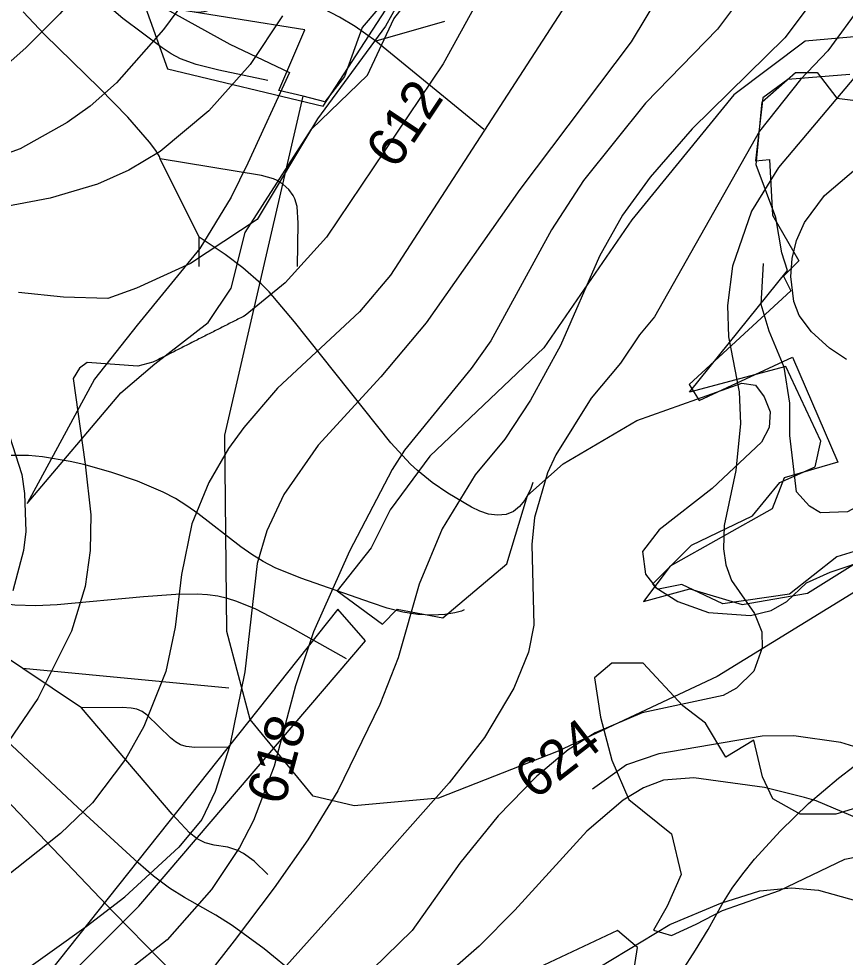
# Model space of a CAD drawing. Extents: x -709584 to -702006, y -1161789 to -1157496.
# Drawn here: x -706673 to -706462.3, y -1159575.6 to -1159336.3 of the extents above; entities that cross this region are included whole.
import ezdxf

# ---------------------------------------------------------------- set-up
doc = ezdxf.new("R2010")
doc.units = 0
for name, color, linetype in [('102_obvod PÚ', 7, 'Continuous'), ('120_vrstevnice hlavní', 7, 'Continuous'), ('121_vrstevnice hlavní_popis', 7, 'Continuous'), ('122_vrstevnice základní', 7, 'Continuous'), ('124_vrstevnice doplňková', 7, 'Continuous'), ('408_BPEJ_linie', 7, 'Continuous'), ('411_akumulovaný odtok', 7, 'Continuous'), ('419_LPIS PB', 7, 'Continuous')]:
    doc.layers.add(name, color=color, linetype=linetype)

msp = doc.modelspace()

# ---------------------------------------------------------------- linework, layer by layer
at = {"layer": '102_obvod PÚ'}
for points in [[(-706646.77, -1159316.53), (-706635.13, -1159349.04), (-706595.43, -1159358.62), (-706572.12, -1159322.59)], [(-706461.16, -1159350.51), (-706476.96, -1159351.76), (-706483.3, -1159356.44), (-706485.18, -1159372.52), (-706481.64, -1159372.18), (-706480.87, -1159386.41), (-706474.14, -1159398.05), (-706478.05, -1159401.96), (-706476.22, -1159405.66), (-706502.09, -1159429.53), (-706499.55, -1159433.61), (-706475.77, -1159422.55), (-706464.19, -1159449.36), (-706477.88, -1159453.35), (-706480.96, -1159461.22), (-706506.97, -1159475.88), (-706513.77, -1159484.9), (-706501.93, -1159481.65), (-706488.59, -1159485.65), (-706471.9, -1159482.71), (-706457.67, -1159473.84)]]:
    msp.add_lwpolyline(points, dxfattribs=at)
at = {"layer": '120_vrstevnice hlavní'}
for points in [[(-706453.14, -1159180.31), (-706463.44, -1159182.02), (-706488.89, -1159188.6), (-706508.34, -1159196.75), (-706527.79, -1159207.05), (-706541.24, -1159216.63), (-706548.67, -1159223.5), (-706554.82, -1159230.94), (-706559.26, -1159240.37), (-706560.97, -1159245.81), (-706562.12, -1159255.53), (-706560.97, -1159270.12), (-706561.12, -1159289.57), (-706563.83, -1159304.16), (-706566.98, -1159313.88), (-706571.41, -1159323.61), (-706579.56, -1159338.2), (-706596.87, -1159361.79), (-706612.27, -1159387.45)], [(-706472.3, -1159333.91), (-706477.74, -1159341.2), (-706501.34, -1159364.37), (-706512.06, -1159376.67), (-706519.07, -1159386.39), (-706524.93, -1159396.83), (-706534.94, -1159419.57), (-706542.52, -1159433.58), (-706549.1, -1159443.45), (-706556.68, -1159452.61), (-706565.12, -1159466.33), (-706570.98, -1159480.49), (-706576.28, -1159499.23), (-706580.99, -1159511.1), (-706591.69, -1159533.16), (-706599.36, -1159545.61), (-706607.91, -1159557.89), (-706618.07, -1159571.37), (-706627.76, -1159583.84)], [(-706612.27, -1159387.46), (-706629.24, -1159398.66), (-706643.01, -1159405.02)], [(-706643.01, -1159405.02), (-706650.29, -1159407.66), (-706661.58, -1159407.24), (-706673.06, -1159406.06)], [(-706675.4, -1159442.75), (-706672.26, -1159452.47), (-706671.55, -1159457.32), (-706671.26, -1159467.04), (-706671.83, -1159471.9), (-706674.55, -1159482.18)]]:
    msp.add_lwpolyline(points, dxfattribs=at)
msp.add_open_spline([(-706612.27, -1159387.45), (-706612.27, -1159387.46)], degree=1, dxfattribs=at)
at = {"layer": '122_vrstevnice základní'}
for points in [[(-706448.85, -1159190.89), (-706463.72, -1159192.18), (-706495.9, -1159204.33), (-706525.65, -1159220.92), (-706535.66, -1159230.36), (-706540.67, -1159237.23), (-706543.67, -1159246.38), (-706544.81, -1159257.82), (-706543.81, -1159287.57), (-706545.24, -1159301.3), (-706549.96, -1159317.32), (-706555.68, -1159331.04), (-706564.83, -1159347.78), (-706594.53, -1159392.02), (-706605.09, -1159403.59), (-706615.32, -1159411.99)], [(-706450, -1159202.05), (-706465.44, -1159204.05), (-706477.02, -1159208.91), (-706485.89, -1159213.92), (-706495.76, -1159218.49), (-706509.77, -1159227.65), (-706514.21, -1159232.08), (-706520.36, -1159241.23), (-706522.36, -1159245.81), (-706524.65, -1159257.25), (-706524.22, -1159266.4), (-706521.21, -1159284.71), (-706520.79, -1159298.44), (-706521.93, -1159306.59), (-706526.51, -1159319.6), (-706532.51, -1159331.04), (-706578.28, -1159401.69), (-706586.14, -1159410.99), (-706607.09, -1159430.51), (-706615.66, -1159440.48), (-706619.55, -1159445.89)], [(-706590.33, -1159211.59), (-706594.67, -1159221.73), (-706609.26, -1159257.6), (-706614.97, -1159269.6), (-706620.54, -1159279.31), (-706635.83, -1159302.6), (-706648.12, -1159318.17), (-706662.55, -1159335.03), (-706671.26, -1159343.75), (-706679.55, -1159351.03), (-706688.69, -1159357.75), (-706694.69, -1159361.32), (-706708.98, -1159367.75), (-706726.12, -1159373.03), (-706741.26, -1159376.46), (-706746.98, -1159378.75), (-706754.27, -1159383.75), (-706758.41, -1159388.32), (-706761.12, -1159393.32), (-706761.12, -1159398.46), (-706758.27, -1159408.46), (-706754.12, -1159416.46), (-706746.27, -1159438.04)], [(-706621.3, -1159318.96), (-706636.1, -1159339.04), (-706648.12, -1159352.6), (-706654.83, -1159358.6), (-706660.69, -1159362.75), (-706672.69, -1159369.46), (-706686.69, -1159374.46)], [(-706505.91, -1159323.89), (-706516.93, -1159342.2), (-706545.24, -1159379.81), (-706569.12, -1159413.85), (-706580.71, -1159427.58), (-706596.73, -1159445.03), (-706605.45, -1159457.61), (-706609.82, -1159466.82), (-706612.21, -1159475.19), (-706615.4, -1159502.81), (-706619.19, -1159521.55), (-706622.98, -1159533.3), (-706626.37, -1159540.48), (-706632.23, -1159547.55)], [(-706458.15, -1159332.76), (-706466.73, -1159344.49), (-706473.73, -1159351.78), (-706484.18, -1159364.94), (-706510.92, -1159412.28), (-706514.78, -1159416.85), (-706519.64, -1159424.15), (-706527.08, -1159433.01), (-706536.09, -1159447.46), (-706538.23, -1159452.03), (-706541.52, -1159463.48), (-706542.24, -1159470.34), (-706541.67, -1159490.93), (-706543.1, -1159497.8), (-706546.82, -1159506.95), (-706554.25, -1159519.54), (-706563.26, -1159531.12), (-706587.83, -1159558.83), (-706605.57, -1159578.52), (-706619.76, -1159593.82)], [(-706605.8, -1159335.59), (-706614.06, -1159347.93), (-706624.59, -1159359.77), (-706636.97, -1159370.18), (-706644.97, -1159374.89), (-706652.97, -1159378.46), (-706664.98, -1159382.03), (-706710.41, -1159390.61)], [(-706491.33, -1159334.19), (-706494.9, -1159338.91), (-706513.21, -1159357.79), (-706529.08, -1159377.52), (-706537.23, -1159390.11), (-706552.68, -1159418.43), (-706557.68, -1159425.43), (-706574.7, -1159446.31), (-706577.85, -1159451.18), (-706588.72, -1159472.06), (-706597.87, -1159492.65), (-706602.45, -1159506.38), (-706607.89, -1159526.89), (-706613.17, -1159540.7), (-706616.75, -1159547.57), (-706623.9, -1159558.29), (-706635.18, -1159571.18)], [(-706457.43, -1159348.21), (-706479.31, -1159374.24), (-706486.18, -1159385.39), (-706491.04, -1159399.41), (-706492.33, -1159409.42), (-706492.04, -1159417.43), (-706489.32, -1159431.44), (-706489.04, -1159439.45), (-706490.18, -1159451.46), (-706493.19, -1159465.48), (-706493.33, -1159471.48), (-706492.76, -1159475.49), (-706491.33, -1159479.49), (-706485.46, -1159487.93), (-706483.6, -1159492.65), (-706483.46, -1159496.65), (-706485.6, -1159502.66), (-706490.04, -1159506.95), (-706493.47, -1159508.81), (-706514.07, -1159513.24), (-706526.08, -1159518.39), (-706532.94, -1159522.68), (-706540.95, -1159529.4), (-706550.82, -1159539.56), (-706560.54, -1159551.57), (-706572.7, -1159568.73), (-706586.14, -1159581.89)], [(-706462.01, -1159423.15), (-706466.3, -1159420.28), (-706470.88, -1159416.14), (-706474.02, -1159411.99), (-706475.45, -1159408.42), (-706476.17, -1159401.98), (-706475.88, -1159397.4), (-706474.74, -1159392.83), (-706472.73, -1159388.25), (-706467.58, -1159381.39), (-706451, -1159367.23)], [(-706638.83, -1159423.89), (-706642.67, -1159424.85), (-706655.58, -1159423.93), (-706657.54, -1159425.41), (-706659.12, -1159428.03), (-706656.12, -1159449.89)], [(-706619.55, -1159445.89), (-706624.59, -1159454.52), (-706628.86, -1159465.05), (-706631.5, -1159477.96), (-706633.14, -1159491.38), (-706635.55, -1159502.75), (-706641.12, -1159516.75), (-706645.83, -1159525.04), (-706654.26, -1159536.18), (-706662.4, -1159544.04), (-706676.4, -1159555.18), (-706692.69, -1159566.19), (-706699.83, -1159571.9), (-706705.34, -1159576.78), (-706711.29, -1159582.62)], [(-706656.12, -1159449.89), (-706654.69, -1159462.75), (-706654.83, -1159471.9), (-706656.12, -1159481.04), (-706659.55, -1159492.47), (-706668.12, -1159509.61), (-706678.12, -1159524.04), (-706689.55, -1159537.18), (-706697.83, -1159544.61), (-706711.55, -1159554.61), (-706730.35, -1159570.68), (-706739.13, -1159579.22)], [(-706355.55, -1159626.14), (-706361.94, -1159611.03), (-706370.77, -1159595.62), (-706381.92, -1159582.89), (-706393.36, -1159573.74), (-706402.51, -1159568.59), (-706423.11, -1159559.15), (-706445.99, -1159545.71), (-706469.73, -1159535.7), (-706472.73, -1159534.84), (-706482.89, -1159532.27), (-706500.91, -1159529.83), (-706508.63, -1159530.41), (-706513.78, -1159532.41), (-706518.93, -1159535.55), (-706528.22, -1159543.42), (-706546.53, -1159563.58), (-706555.68, -1159572.74), (-706584.55, -1159598.12)], [(-706681.48, -1159586.27), (-706673.81, -1159580.61), (-706655.85, -1159567.77), (-706645.98, -1159560.2), (-706632.23, -1159547.55)], [(-706561.35, -1159600.93), (-706525.29, -1159578.32), (-706507.07, -1159567.2), (-706494.06, -1159561.76), (-706484.12, -1159558.68), (-706476.02, -1159557.86), (-706469.16, -1159558.44), (-706455.43, -1159562.3), (-706429.69, -1159575.6), (-706412.38, -1159582.75), (-706401.37, -1159588.47), (-706396.22, -1159593.05), (-706388.79, -1159601.05), (-706383.92, -1159607.92), (-706375.74, -1159623.67)], [(-706635.18, -1159571.18), (-706645.15, -1159578.94), (-706652.86, -1159583.9), (-706660.95, -1159588.78)]]:
    msp.add_lwpolyline(points, dxfattribs=at)
for points in [[(-706615.33, -1159411.99), (-706638.83, -1159423.89)], [(-706615.32, -1159411.99), (-706615.33, -1159411.99)], [(-706619.55, -1159445.89), (-706619.55, -1159445.89)], [(-706632.23, -1159547.55), (-706632.23, -1159547.55)], [(-706635.18, -1159571.18), (-706635.18, -1159571.18)]]:
    msp.add_open_spline(points, degree=1, dxfattribs=at)
at = {"layer": '124_vrstevnice doplňková'}
for points in [[(-706440.84, -1159431.58), (-706448.42, -1159442.31), (-706455.43, -1159456.04), (-706458.58, -1159460.33), (-706461.72, -1159462.04), (-706468.63, -1159462.31), (-706471.45, -1159460.61), (-706474.73, -1159456.9), (-706476.45, -1159442.59), (-706476.45, -1159434.3), (-706477.88, -1159425.15), (-706481.74, -1159415.99), (-706483.75, -1159409.13), (-706483.17, -1159398.69)], [(-706397.22, -1159559.29), (-706425.97, -1159541.56), (-706443.7, -1159528.83), (-706454.57, -1159523.54), (-706463.44, -1159520.82), (-706475.45, -1159519.11), (-706483.46, -1159519.25), (-706509.8, -1159523.7), (-706518.07, -1159526.54), (-706526.79, -1159532.69)]]:
    msp.add_lwpolyline(points, dxfattribs=at)
at = {"layer": '408_BPEJ_linie'}
for points in [[(-706433.5, -1159301.5), (-706463, -1159305.5), (-706463.72, -1159304.98), (-706463.8, -1159304.2), (-706466.32, -1159303.1), (-706475.32, -1159296.61), (-706476.4, -1159295.5), (-706483.5, -1159289.2), (-706489.1, -1159282.1), (-706490.76, -1159280.86), (-706494, -1159277), (-706507.37, -1159266.01), (-706511.1, -1159261.6), (-706511.7, -1159262.44), (-706516.5, -1159258.5), (-706553, -1159301.5), (-706570, -1159315), (-706577, -1159328.5), (-706585.5, -1159338.5), (-706590, -1159351), (-706595, -1159357.5), (-706600.5, -1159356)], [(-706600.5, -1159356), (-706606.7, -1159354.59), (-706600.1, -1159339.1), (-706636.27, -1159333.33)], [(-706443.5, -1159467), (-706464.5, -1159473.5), (-706476.5, -1159483), (-706493.5, -1159485.5), (-706504, -1159480.5), (-706509.94, -1159481.75), (-706510.48, -1159481.4), (-706511.33, -1159480.33), (-706501.5, -1159470.5), (-706486, -1159463), (-706479, -1159454.5), (-706470, -1159450.5), (-706468.5, -1159444), (-706477.5, -1159425), (-706502, -1159431.5), (-706477, -1159400.5), (-706478.5, -1159396), (-706480, -1159387), (-706485, -1159373.5), (-706483.5, -1159357.5), (-706475, -1159350), (-706469.5, -1159350), (-706464.5, -1159356.5), (-706457, -1159357.5)], [(-706324.5, -1159717), (-706335, -1159689), (-706349.5, -1159593), (-706369, -1159549.5), (-706397.5, -1159509), (-706407.5, -1159475.5), (-706418, -1159463), (-706431.5, -1159465), (-706495, -1159504), (-706535.5, -1159523), (-706566, -1159535), (-706587.5, -1159537), (-706598, -1159534.5), (-706614, -1159515), (-706620, -1159492.5), (-706620.5, -1159442.5), (-706600.5, -1159356)]]:
    msp.add_lwpolyline(points, dxfattribs=at)
at = {"layer": '411_akumulovaný odtok'}
for p, q in [((-706564.49, -1159337), (-706581.99, -1159342)), ((-706554.49, -1159364.5), (-706581.99, -1159342)), ((-706626.99, -1159392), (-706636.99, -1159372)), ((-706626.99, -1159399.5), (-706626.99, -1159392)), ((-706619.49, -1159507), (-706671.99, -1159502)), ((-706656.99, -1159512), (-706671.99, -1159502))]:
    msp.add_line(p, q, dxfattribs=at)
for points in [[(-706581.99, -1159342), (-706587.3, -1159338.31), (-706591.22, -1159335.86), (-706595.32, -1159333.76), (-706597.26, -1159333.03), (-706599.15, -1159332.58), (-706604.77, -1159332.06), (-706612.38, -1159332.14), (-706616.12, -1159332.41), (-706619.71, -1159332.92), (-706625.82, -1159334.51), (-706627.24, -1159334.67), (-706628.78, -1159334.55), (-706630.33, -1159334.17), (-706633.46, -1159332.88), (-706638.22, -1159330.25), (-706666.99, -1159312)], [(-706609.49, -1159352), (-706622.05, -1159349.37), (-706627.78, -1159347.95), (-706631.76, -1159346.5), (-706634.15, -1159345.2), (-706636.46, -1159343.7), (-706646.48, -1159336.25), (-706651.73, -1159331.76), (-706653.6, -1159329.73), (-706656.21, -1159326.51), (-706666.99, -1159312)], [(-706636.99, -1159372), (-706637.17, -1159371.39), (-706638.1, -1159369.91), (-706639.69, -1159367.75), (-706645.2, -1159361.41), (-706652.48, -1159353.96), (-706666.5, -1159340.3), (-706671.9, -1159334.54)], [(-706601.99, -1159399.5), (-706601.76, -1159388.41), (-706602.08, -1159384.13), (-706602.65, -1159382.18), (-706603.08, -1159381.36), (-706604.21, -1159379.87), (-706605.59, -1159378.58), (-706607.18, -1159377.53), (-706608.12, -1159377.1), (-706611.17, -1159376.23), (-706636.99, -1159372)], [(-706541.99, -1159454.5), (-706542.47, -1159456.04), (-706543.14, -1159457.49), (-706544.1, -1159459.1), (-706545.33, -1159460.64), (-706546.85, -1159461.89), (-706548.8, -1159462.68), (-706550.97, -1159462.88), (-706553.24, -1159462.58), (-706555.48, -1159461.86), (-706557.57, -1159460.85), (-706563.67, -1159457.22), (-706567.64, -1159454.51), (-706571.4, -1159451.51), (-706573.18, -1159449.83), (-706578.13, -1159444.39), (-706602.75, -1159413.54), (-706609.19, -1159405.95), (-706611.26, -1159403.86), (-706615.86, -1159399.83), (-706620.44, -1159396.39), (-706626.99, -1159392)], [(-706559.49, -1159487), (-706560.13, -1159487.34), (-706561.83, -1159487.77), (-706564.38, -1159488.17), (-706567.59, -1159488.38), (-706571.27, -1159488.22), (-706575.11, -1159487.59), (-706579.08, -1159486.55), (-706583.1, -1159485.25), (-706601.15, -1159478.94), (-706607.63, -1159476.28), (-706610.74, -1159474.68), (-706613.63, -1159472.89), (-706616.43, -1159470.91), (-706627.35, -1159462.45), (-706630.16, -1159460.46), (-706633.07, -1159458.63), (-706636.19, -1159456.96), (-706642.74, -1159454.17), (-706649.53, -1159451.87), (-706656.45, -1159449.95), (-706659.94, -1159449.15), (-706666.93, -1159447.99), (-706670.53, -1159447.68), (-706677.65, -1159447.65)], [(-706579.49, -1159629.5), (-706583.27, -1159624.18), (-706589.17, -1159616.82), (-706592.75, -1159612.79), (-706596.59, -1159608.78), (-706600.53, -1159604.99), (-706604.42, -1159601.59), (-706608.08, -1159598.79), (-706617.81, -1159592.6), (-706620.99, -1159590.44), (-706624.32, -1159587.9), (-706630.69, -1159582.34), (-706636.82, -1159576.42), (-706648.8, -1159564.13), (-706731.99, -1159477)], [(-706589.49, -1159499.5), (-706603.81, -1159491.42), (-706612.59, -1159486.87), (-706617.42, -1159484.86), (-706619.83, -1159484.08), (-706622.29, -1159483.5), (-706624.92, -1159483.14), (-706627.58, -1159482.99), (-706633, -1159483.07), (-706641.22, -1159483.69), (-706663.23, -1159485.73), (-706668.68, -1159485.97), (-706674.05, -1159485.81), (-706676.69, -1159485.46), (-706681.33, -1159484.28), (-706692.71, -1159479.99), (-706697.59, -1159478.5), (-706700.88, -1159477.89), (-706708.06, -1159477.19), (-706714.88, -1159476.96), (-706721.99, -1159477)], [(-706671.99, -1159502), (-706681.13, -1159495.8), (-706685.4, -1159493.34), (-706688.13, -1159492.44), (-706694.87, -1159491.69), (-706696.66, -1159491.19), (-706697.5, -1159490.78), (-706699.82, -1159489.08), (-706704.93, -1159484.36), (-706707.32, -1159482.76), (-706708.33, -1159482.43), (-706710.76, -1159482.04), (-706716.99, -1159482)], [(-706524.49, -1159674.5), (-706525.18, -1159673.85), (-706526.52, -1159671.64), (-706533.03, -1159658.66), (-706535.98, -1159653.09), (-706539.31, -1159647.41), (-706542.91, -1159641.82), (-706546.62, -1159636.5), (-706550.27, -1159631.66), (-706556.98, -1159623.59), (-706563.82, -1159615.99), (-706571.08, -1159608.51), (-706578.73, -1159601.16), (-706590.47, -1159590.41), (-706602.37, -1159580.03), (-706610.42, -1159573.47), (-706618.62, -1159567.48), (-706622.8, -1159564.81), (-706630.76, -1159560.32), (-706634.59, -1159557.94), (-706638.65, -1159554.87), (-706642.57, -1159551.49), (-706657.95, -1159537.41), (-706716.99, -1159482)], [(-706619.49, -1159522), (-706628.12, -1159522.11), (-706630.36, -1159521.85), (-706631.75, -1159521.43), (-706633.08, -1159520.63), (-706634.32, -1159519.61), (-706640.26, -1159513.86), (-706641.54, -1159512.94), (-706642.91, -1159512.33), (-706644.37, -1159512.04), (-706646.67, -1159511.89), (-706656.99, -1159512)], [(-706609.49, -1159554.5), (-706613.04, -1159551.12), (-706615.71, -1159549.17), (-706617.13, -1159548.4), (-706619.72, -1159547.55), (-706623.22, -1159546.98), (-706625.47, -1159546.43), (-706627.57, -1159545.4), (-706629.49, -1159543.85), (-706633.89, -1159539.11), (-706656.99, -1159512)], [(-706519.49, -1159599.5), (-706516.99, -1159596.64), (-706511.22, -1159589.21), (-706504.01, -1159579.18), (-706500.47, -1159573.8), (-706497.28, -1159568.52), (-706493.72, -1159562.04), (-706491.18, -1159557.99), (-706488.46, -1159554.29), (-706485.45, -1159550.61), (-706478.84, -1159543.38), (-706471.67, -1159536.4), (-706464.04, -1159529.88), (-706460.02, -1159526.89)]]:
    msp.add_lwpolyline(points, dxfattribs=at)
at = {"layer": '419_LPIS PB'}
for points in [[(-706636.27, -1159333.33), (-706619.17, -1159342.81), (-706603.98, -1159350.04), (-706614.6, -1159373.1), (-706618.9, -1159381.8), (-706626.9, -1159394.9), (-706642.8, -1159414.4), (-706653.7, -1159428.2), (-706670.86, -1159459.86), (-706647.04, -1159431.71), (-706638.33, -1159424.25), (-706624.7, -1159413.7), (-706618.9, -1159405), (-706615.29, -1159390.79), (-706598.4, -1159364.44), (-706584.1, -1159350.7), (-706577.4, -1159336.35), (-706548.57, -1159299.46)], [(-706455.2, -1159340.5), (-706472.5, -1159342), (-706490.7, -1159355.7), (-706516.7, -1159387.6), (-706539.2, -1159420.2), (-706568.2, -1159447.8), (-706578.3, -1159461.5), (-706583.2, -1159471.22), (-706591.88, -1159482.17), (-706580.3, -1159490.67), (-706576.54, -1159486.83), (-706564.9, -1159489), (-706548.6, -1159475.3), (-706543.28, -1159457.81), (-706534.27, -1159449.78), (-706515.49, -1159438.73), (-706488.7, -1159429.2), (-706485.2, -1159429.7), (-706482.95, -1159432.71), (-706481.44, -1159436.48), (-706481.7, -1159440.49), (-706483.7, -1159444.26), (-706496.21, -1159456.05), (-706509.73, -1159466.59), (-706513.99, -1159472.11), (-706513.24, -1159477.89), (-706510.48, -1159481.4), (-706504.98, -1159484.91), (-706497.21, -1159487.67), (-706486.45, -1159488.43), (-706481.19, -1159487.17), (-706477.19, -1159484.91), (-706472.18, -1159480.15), (-706466.17, -1159477.38), (-706444.65, -1159470.19)], [(-706662.56, -1159582.7), (-706642.45, -1159562.59), (-706584.61, -1159494.92), (-706591.64, -1159486.84), (-706665.38, -1159579.53)], [(-706458.36, -1159537.17), (-706464.72, -1159539.13), (-706473.77, -1159539.1), (-706480.79, -1159535.22), (-706483.4, -1159529.6), (-706485.6, -1159520.2), (-706492.8, -1159524.6), (-706497.9, -1159515.9), (-706503.7, -1159511.5), (-706513.8, -1159500.6), (-706521.8, -1159500.6), (-706526.2, -1159504.3), (-706524.7, -1159514.4), (-706521.8, -1159525.3), (-706517.5, -1159535.4), (-706506.6, -1159544.1), (-706504.16, -1159554.48), (-706507.69, -1159562.59), (-706511.19, -1159568.64), (-706506.63, -1159570), (-706500.28, -1159567.18), (-706493.6, -1159563.7), (-706479.1, -1159558.6), (-706462.4, -1159550.6), (-706434.1, -1159544.8)], [(-706517.25, -1159585.68), (-706515.3, -1159573.1), (-706520.4, -1159568.8), (-706543.5, -1159579.6)]]:
    msp.add_lwpolyline(points, dxfattribs=at)

# ---------------------------------------------------------------- texts
at = {"layer": '121_vrstevnice hlavní_popis'}
for s, rotation, p in [('612', 56.3215, (-706576.85, -1159375)), ('618', 74.8468, (-706605.44, -1159537.16)), ('624', 37.8572, (-706541.47, -1159535.63))]:
    msp.add_text(s, height=10, rotation=rotation, dxfattribs=at).set_placement(p)

doc.saveas('drawing.dxf')
